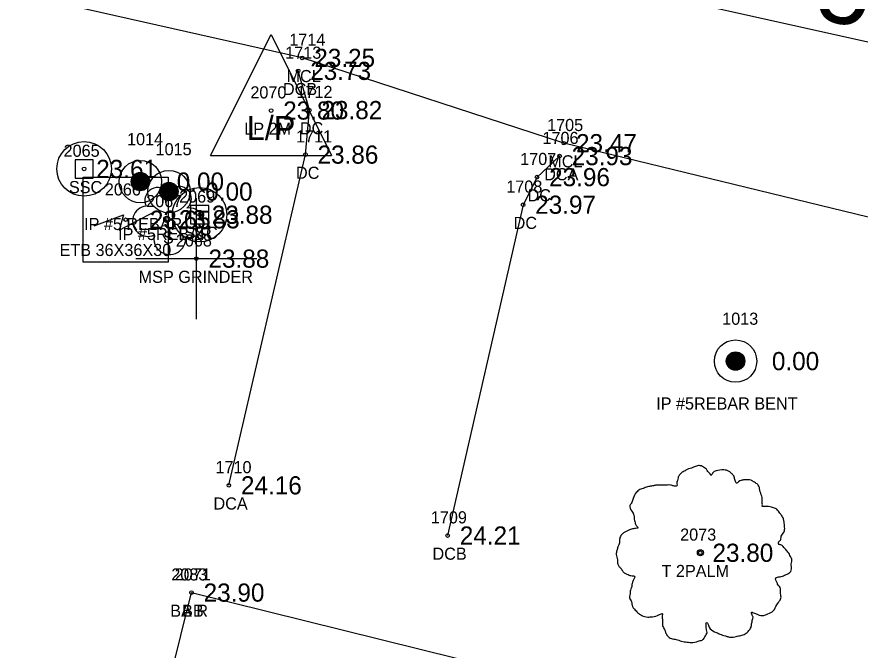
# Model space of a CAD drawing. Extents: x 2654414 to 2656963, y 761776 to 764965.
# Drawn here: x 2655340.6 to 2655410.2, y 762159.7 to 762212 of the extents above; entities that cross this region are included whole.
import ezdxf

# ---------------------------------------------------------------- set-up
doc = ezdxf.new("R2010")
doc.units = 0
for name, color, linetype in [('RD_EX_Bldg', 7, 'Continuous'), ('RD_EX_Bldg_txCode', 7, 'Continuous'), ('RD_EX_Conc', 7, 'Continuous'), ('RD_EX_Conc_txCode', 7, 'Continuous'), ('RD_EX_DV_Prop_txCode', 7, 'Continuous'), ('RD_EX_DV_PropPin', 7, 'Continuous'), ('RD_EX_Misc', 7, 'Continuous'), ('RD_EX_Misc_txCode', 7, 'Continuous'), ('RD_EX_TX_Bldg_ELEV', 7, 'Continuous'), ('RD_EX_TX_Conc_ELEV', 7, 'Continuous'), ('RD_EX_TX_DV_Prop_ELEV', 7, 'Continuous'), ('RD_EX_TX_Misc_ELEV', 7, 'Continuous'), ('RD_EX_TX_UT_ELEV', 7, 'Continuous'), ('RD_EX_TX_VEG_ELEV', 7, 'Continuous'), ('RD_EX_UT', 7, 'Continuous'), ('RD_EX_UT_txCode', 7, 'Continuous'), ('RD_EX_VEG', 7, 'Continuous'), ('RD_EX_VEG_txCode', 7, 'Continuous'), ('RD_HC_Cl', 7, 'Continuous'), ('RD_HC_Data', 7, 'Continuous'), ('RD_SMD_Locator', 7, 'Continuous')]:
    doc.layers.add(name, color=color, linetype=linetype)

msp = doc.modelspace()

# ---------------------------------------------------------------- linework, layer by layer
at = {"layer": 'RD_EX_Bldg'}
msp.add_lwpolyline([(2655355.022, 762164.47), (2655405.088, 762152.061), (2655393.54, 762105.47), (2655343.474, 762117.88), (2655355.022, 762164.47)], dxfattribs=at)
at = {"layer": 'RD_EX_Conc'}
for points in [[(2655440.54, 762187.622), (2655439.059, 762188.617), (2655385.758, 762201.571), (2655364.155, 762208.612), (2655337.932, 762214.524), (2655306.963, 762222.49), (2655288.125, 762231.245)], [(2655358.103, 762173.325), (2655364.425, 762200.628), (2655364.748, 762204.303), (2655363.82, 762207.541)], [(2655385.399, 762200.505), (2655383.539, 762198.768), (2655382.389, 762196.489), (2655376.164, 762169.181)]]:
    msp.add_lwpolyline(points, dxfattribs=at)
at = {"layer": 'RD_EX_DV_PropPin'}
for p, q in [((2655350.102, 762198.103), (2655350.102, 762198.699)), ((2655350.137, 762198.032), (2655350.137, 762198.771)), ((2655350.172, 762197.975), (2655350.172, 762198.828)), ((2655350.207, 762197.927), (2655350.207, 762198.875)), ((2655350.242, 762197.886), (2655350.242, 762198.916)), ((2655350.277, 762197.851), (2655350.277, 762198.952)), ((2655350.312, 762197.819), (2655350.312, 762198.983)), ((2655350.347, 762197.791), (2655350.347, 762199.011)), ((2655350.382, 762197.767), (2655350.382, 762199.036)), ((2655350.417, 762197.745), (2655350.417, 762199.058)), ((2655350.452, 762197.726), (2655350.452, 762199.077)), ((2655350.487, 762197.709), (2655350.487, 762199.094)), ((2655350.522, 762197.694), (2655350.522, 762199.109)), ((2655350.557, 762197.681), (2655350.557, 762199.122)), ((2655350.592, 762197.67), (2655350.592, 762199.133)), ((2655350.627, 762197.661), (2655350.627, 762199.142)), ((2655350.662, 762197.653), (2655350.662, 762199.149)), ((2655350.697, 762197.648), (2655350.697, 762199.155)), ((2655350.732, 762197.644), (2655350.732, 762199.159)), ((2655350.767, 762197.641), (2655350.767, 762199.162)), ((2655350.802, 762197.64), (2655350.802, 762199.162)), ((2655350.837, 762197.641), (2655350.837, 762199.162)), ((2655350.872, 762197.644), (2655350.872, 762199.159)), ((2655350.907, 762197.648), (2655350.907, 762199.155)), ((2655350.942, 762197.653), (2655350.942, 762199.149)), ((2655350.977, 762197.661), (2655350.977, 762199.142)), ((2655351.012, 762197.67), (2655351.012, 762199.133)), ((2655351.047, 762197.681), (2655351.047, 762199.122)), ((2655351.082, 762197.694), (2655351.082, 762199.109)), ((2655351.117, 762197.709), (2655351.117, 762199.094)), ((2655351.152, 762197.726), (2655351.152, 762199.077)), ((2655351.187, 762197.745), (2655351.187, 762199.058)), ((2655351.222, 762197.767), (2655351.222, 762199.036)), ((2655351.257, 762197.791), (2655351.257, 762199.011)), ((2655351.292, 762197.819), (2655351.292, 762198.983)), ((2655351.327, 762197.851), (2655351.327, 762198.952)), ((2655351.362, 762197.886), (2655351.362, 762198.916)), ((2655351.397, 762197.927), (2655351.397, 762198.875)), ((2655351.432, 762197.975), (2655351.432, 762198.828)), ((2655351.467, 762198.032), (2655351.467, 762198.771)), ((2655351.502, 762198.103), (2655351.502, 762198.699)), ((2655350.067, 762198.205), (2655350.067, 762198.597)), ((2655351.537, 762198.205), (2655351.537, 762198.597)), ((2655352.528, 762197.15), (2655352.528, 762198.003)), ((2655352.563, 762197.102), (2655352.563, 762198.051)), ((2655352.598, 762197.061), (2655352.598, 762198.091)), ((2655352.633, 762197.026), (2655352.633, 762198.127)), ((2655352.668, 762196.994), (2655352.668, 762198.159)), ((2655352.703, 762196.967), (2655352.703, 762198.186)), ((2655352.738, 762196.942), (2655352.738, 762198.211)), ((2655352.773, 762196.92), (2655352.773, 762198.233)), ((2655352.808, 762196.901), (2655352.808, 762198.252)), ((2655352.843, 762196.884), (2655352.843, 762198.269)), ((2655352.878, 762196.869), (2655352.878, 762198.284)), ((2655352.913, 762196.856), (2655352.913, 762198.297)), ((2655352.948, 762196.845), (2655352.948, 762198.308)), ((2655352.983, 762196.836), (2655352.983, 762198.317)), ((2655353.018, 762196.828), (2655353.018, 762198.324)), ((2655353.053, 762196.823), (2655353.053, 762198.33)), ((2655353.088, 762196.819), (2655353.088, 762198.334)), ((2655353.123, 762196.816), (2655353.123, 762198.337)), ((2655353.158, 762196.815), (2655353.158, 762198.337)), ((2655353.193, 762196.816), (2655353.193, 762198.337)), ((2655353.228, 762196.819), (2655353.228, 762198.334)), ((2655353.263, 762196.823), (2655353.263, 762198.33)), ((2655353.298, 762196.828), (2655353.298, 762198.324)), ((2655353.333, 762196.836), (2655353.333, 762198.317)), ((2655353.368, 762196.845), (2655353.368, 762198.308)), ((2655353.403, 762196.856), (2655353.403, 762198.297)), ((2655353.438, 762196.869), (2655353.438, 762198.284)), ((2655353.474, 762196.884), (2655353.474, 762198.269)), ((2655353.509, 762196.901), (2655353.509, 762198.252)), ((2655353.544, 762196.92), (2655353.544, 762198.233)), ((2655353.579, 762196.942), (2655353.579, 762198.211)), ((2655353.614, 762196.967), (2655353.614, 762198.186)), ((2655353.649, 762196.994), (2655353.649, 762198.159)), ((2655353.684, 762197.026), (2655353.684, 762198.127)), ((2655353.719, 762197.061), (2655353.719, 762198.091)), ((2655353.754, 762197.102), (2655353.754, 762198.051)), ((2655353.789, 762197.15), (2655353.789, 762198.003)), ((2655352.423, 762197.38), (2655352.423, 762197.773)), ((2655352.458, 762197.278), (2655352.458, 762197.874)), ((2655352.493, 762197.207), (2655352.493, 762197.946)), ((2655353.824, 762197.207), (2655353.824, 762197.946)), ((2655353.859, 762197.278), (2655353.859, 762197.874)), ((2655353.894, 762197.38), (2655353.894, 762197.773)), ((2655399.331, 762183.105), (2655399.331, 762184.054)), ((2655399.366, 762183.064), (2655399.366, 762184.095)), ((2655399.401, 762183.029), (2655399.401, 762184.13)), ((2655399.436, 762182.997), (2655399.436, 762184.162)), ((2655399.471, 762182.97), (2655399.471, 762184.189)), ((2655399.506, 762182.945), (2655399.506, 762184.214)), ((2655399.541, 762182.923), (2655399.541, 762184.236)), ((2655399.576, 762182.904), (2655399.576, 762184.255)), ((2655399.611, 762182.887), (2655399.611, 762184.272)), ((2655399.646, 762182.872), (2655399.646, 762184.287)), ((2655399.681, 762182.859), (2655399.681, 762184.3)), ((2655399.716, 762182.848), (2655399.716, 762184.311)), ((2655399.751, 762182.839), (2655399.751, 762184.32)), ((2655399.786, 762182.831), (2655399.786, 762184.328)), ((2655399.821, 762182.826), (2655399.821, 762184.333)), ((2655399.856, 762182.822), (2655399.856, 762184.337)), ((2655399.891, 762182.819), (2655399.891, 762184.34)), ((2655399.926, 762182.818), (2655399.926, 762184.341)), ((2655399.961, 762182.819), (2655399.961, 762184.34)), ((2655399.996, 762182.822), (2655399.996, 762184.337)), ((2655400.031, 762182.826), (2655400.031, 762184.333)), ((2655400.066, 762182.831), (2655400.066, 762184.328)), ((2655400.101, 762182.839), (2655400.101, 762184.32)), ((2655400.136, 762182.848), (2655400.136, 762184.311)), ((2655400.171, 762182.859), (2655400.171, 762184.3)), ((2655400.206, 762182.872), (2655400.206, 762184.287)), ((2655400.242, 762182.887), (2655400.242, 762184.272)), ((2655400.277, 762182.904), (2655400.277, 762184.255)), ((2655400.312, 762182.923), (2655400.312, 762184.236)), ((2655400.347, 762182.945), (2655400.347, 762184.214)), ((2655400.382, 762182.97), (2655400.382, 762184.189)), ((2655400.417, 762182.997), (2655400.417, 762184.162)), ((2655400.452, 762183.029), (2655400.452, 762184.13)), ((2655400.487, 762183.064), (2655400.487, 762184.095)), ((2655400.522, 762183.105), (2655400.522, 762184.054)), ((2655399.191, 762183.383), (2655399.191, 762183.776)), ((2655399.226, 762183.282), (2655399.226, 762183.877)), ((2655399.261, 762183.21), (2655399.261, 762183.949)), ((2655399.296, 762183.153), (2655399.296, 762184.006)), ((2655400.557, 762183.153), (2655400.557, 762184.006)), ((2655400.592, 762183.21), (2655400.592, 762183.949)), ((2655400.627, 762183.282), (2655400.627, 762183.877)), ((2655400.662, 762183.383), (2655400.662, 762183.776))]:
    msp.add_line(p, q, dxfattribs=at)
for centre, radius in [((2655350.802, 762198.401), 1.75), ((2655350.802, 762198.401), 0.761), ((2655353.158, 762197.576), 1.75), ((2655353.158, 762197.576), 0.761), ((2655399.926, 762183.579), 1.75), ((2655399.926, 762183.579), 0.761)]:
    msp.add_circle(centre, radius, dxfattribs=at)
at = {"layer": 'RD_EX_Misc'}
for p, q in [((2655355.422, 762187.04), (2655355.422, 762197.04)), ((2655350.422, 762192.04), (2655360.422, 762192.04))]:
    msp.add_line(p, q, dxfattribs=at)
at = {"layer": 'RD_EX_UT'}
for p, q in [((2655356.589, 762200.542), (2655361.589, 762210.542)), ((2655361.589, 762210.542), (2655366.589, 762200.542)), ((2655346.905, 762200.196), (2655345.405, 762200.196)), ((2655345.405, 762200.196), (2655345.405, 762198.696)), ((2655346.905, 762198.696), (2655346.905, 762200.196)), ((2655356.589, 762200.542), (2655366.589, 762200.542)), ((2655345.405, 762198.696), (2655346.905, 762198.696)), ((2655356.441, 762196.415), (2655354.941, 762196.415)), ((2655354.941, 762196.415), (2655354.941, 762194.915)), ((2655356.441, 762194.915), (2655356.441, 762196.415)), ((2655354.941, 762194.915), (2655356.441, 762194.915))]:
    msp.add_line(p, q, dxfattribs=at)
msp.add_lwpolyline([(2655346.085, 762191.755), (2655346.085, 762198.755), (2655353.085, 762198.755), (2655353.085, 762191.755)], close=True, dxfattribs=at)
msp.add_lwpolyline([(2655346.983, 762194.749), (2655349.406, 762195.649), (2655349.06, 762194.403), (2655352.105, 762195.996)], dxfattribs=at)
for centre in [(2655346.155, 762199.446), (2655355.691, 762195.665)]:
    msp.add_circle(centre, 2.25, dxfattribs=at)
at = {"layer": 'RD_EX_VEG'}
for centre, radius in [((2655352.975, 762195.29), 0.25), ((2655397.023, 762167.757), 0.25), ((2655397.011, 762167.738), 0.0001)]:
    msp.add_circle(centre, radius, dxfattribs=at)
for centre, radius, start, end in [((2655354.021, 762196.992), 0.995, 308.76261, 152.04674), ((2655352.254, 762196.837), 1.084, 34.97629, 204.75602), ((2655351.412, 762195.134), 1.257, 96.45179, 294.73401), ((2655354.815, 762195.01), 1.218, 256.56668, 98.10463), ((2655353.221, 762193.693), 1.318, 166.88266, 5.75893)]:
    msp.add_arc(centre, radius, start, end, dxfattribs=at)
for points in [[(2655397.155, 762174.924), (2655396.855, 762174.949), (2655396.53, 762174.849), (2655396.28, 762174.749), (2655396.056, 762174.674), (2655395.831, 762174.574), (2655395.531, 762174.399), (2655395.306, 762174.199), (2655395.181, 762173.949), (2655395.131, 762173.724), (2655395.081, 762173.45), (2655395.081, 762173.275), (2655394.956, 762173.25), (2655394.806, 762173.275), (2655394.556, 762173.35), (2655394.306, 762173.35), (2655394.056, 762173.35), (2655393.707, 762173.325), (2655393.357, 762173.325), (2655393.082, 762173.275), (2655392.757, 762173.225), (2655392.382, 762173.1), (2655392.032, 762172.975), (2655391.732, 762172.725), (2655391.483, 762172.25), (2655391.358, 762171.9), (2655391.208, 762171.65), (2655391.358, 762171.201), (2655391.533, 762170.851), (2655391.557, 762170.651), (2655391.632, 762170.226), (2655391.732, 762170.001), (2655391.857, 762169.801), (2655391.782, 762169.776), (2655391.408, 762169.726), (2655391.108, 762169.626), (2655390.683, 762169.401), (2655390.458, 762169.176), (2655390.358, 762168.851), (2655390.333, 762168.502), (2655390.233, 762168.302), (2655390.158, 762168.027), (2655390.133, 762167.952), (2655390.083, 762167.627), (2655390.183, 762167.177), (2655390.208, 762166.827), (2655390.333, 762166.602), (2655390.483, 762166.428), (2655390.658, 762166.178), (2655391.058, 762165.953), (2655391.383, 762165.853), (2655391.582, 762165.828), (2655391.408, 762165.328), (2655391.358, 762164.978), (2655391.233, 762164.578), (2655391.233, 762164.503), (2655391.183, 762164.029), (2655391.333, 762163.704), (2655391.408, 762163.329), (2655391.582, 762163.104), (2655391.857, 762162.804), (2655392.182, 762162.579), (2655392.682, 762162.454), (2655393.082, 762162.479), (2655393.657, 762162.654), (2655393.906, 762162.729), (2655393.881, 762162.554), (2655393.906, 762162.179), (2655393.906, 762161.755), (2655394.056, 762161.43), (2655394.156, 762161.155), (2655394.306, 762160.905), (2655394.631, 762160.68), (2655395.031, 762160.605), (2655395.456, 762160.455), (2655395.906, 762160.38), (2655396.405, 762160.355), (2655397.005, 762160.505), (2655397.28, 762160.63), (2655397.38, 762160.805), (2655397.58, 762161.18), (2655397.53, 762161.405), (2655397.555, 762162.005), (2655397.655, 762161.83), (2655397.83, 762161.48), (2655398.33, 762161.18), (2655398.729, 762161.005), (2655399.204, 762160.855), (2655399.504, 762160.78), (2655399.979, 762160.855), (2655400.354, 762160.93), (2655400.728, 762161.055), (2655401.028, 762161.33), (2655401.203, 762161.605), (2655401.253, 762161.88), (2655401.328, 762162.254), (2655401.378, 762162.429)], [(2655401.378, 762162.429), (2655401.303, 762162.604), (2655401.253, 762162.854), (2655401.328, 762162.829), (2655401.503, 762162.779), (2655401.778, 762162.654), (2655402.003, 762162.579), (2655402.328, 762162.604), (2655402.603, 762162.704), (2655403.052, 762162.979), (2655403.327, 762163.454), (2655403.602, 762163.854), (2655403.677, 762164.179), (2655403.627, 762164.403), (2655403.602, 762164.903), (2655403.402, 762165.153), (2655403.352, 762165.278), (2655403.252, 762165.678), (2655403.327, 762165.728), (2655403.602, 762165.778), (2655403.977, 762165.903), (2655404.252, 762166.028), (2655404.477, 762166.203), (2655404.552, 762166.428), (2655404.527, 762166.827), (2655404.577, 762167.227), (2655404.502, 762167.377), (2655404.402, 762167.527), (2655404.327, 762167.727), (2655404.177, 762167.877), (2655404.077, 762168.027), (2655403.977, 762168.127), (2655403.852, 762168.277), (2655403.677, 762168.402), (2655403.527, 762168.452), (2655403.477, 762168.602), (2655403.627, 762168.802), (2655403.677, 762168.901), (2655403.702, 762169.126), (2655403.927, 762169.476), (2655403.977, 762169.876), (2655403.927, 762170.301), (2655403.877, 762170.576), (2655403.727, 762170.851), (2655403.527, 762171.101), (2655403.402, 762171.275), (2655403.227, 762171.4), (2655402.903, 762171.525), (2655402.653, 762171.575), (2655402.303, 762171.575), (2655402.103, 762171.625), (2655402.128, 762171.675), (2655402.128, 762171.825), (2655402.128, 762172.1), (2655402.053, 762172.55), (2655401.903, 762173.05), (2655401.903, 762173.075), (2655401.803, 762173.325), (2655401.578, 762173.524), (2655401.403, 762173.624), (2655401.203, 762173.749), (2655400.953, 762173.774), (2655400.654, 762173.774), (2655400.379, 762173.724), (2655400.179, 762173.624), (2655400.004, 762173.499), (2655399.929, 762173.649), (2655399.829, 762173.949), (2655399.779, 762174.099), (2655399.629, 762174.274), (2655399.404, 762174.474), (2655398.954, 762174.599), (2655398.33, 762174.524), (2655398.03, 762174.324), (2655397.88, 762174.149), (2655397.83, 762174.274), (2655397.63, 762174.474), (2655397.53, 762174.649), (2655397.355, 762174.774), (2655397.205, 762174.874), (2655397.105, 762174.924)]]:
    msp.add_spline(points, degree=3, dxfattribs=at)
at = {"layer": 'RD_HC_Cl'}
msp.add_line((2655476.255, 762195.138), (2655321.054, 762230.163), dxfattribs=at)
at = {"layer": 'RD_SMD_Locator'}
for centre in [(2655364.155, 762208.612), (2655363.82, 762207.541), (2655361.589, 762204.266), (2655364.748, 762204.303), (2655385.758, 762201.571), (2655364.425, 762200.628), (2655385.399, 762200.505), (2655346.155, 762199.446), (2655383.539, 762198.768), (2655350.802, 762198.401), (2655353.158, 762197.576), (2655382.389, 762196.489), (2655349.585, 762195.255), (2655352.975, 762195.29), (2655355.691, 762195.665), (2655355.422, 762192.04), (2655399.926, 762183.579), (2655358.103, 762173.325), (2655376.164, 762169.181), (2655397.023, 762167.757), (2655355.022, 762164.47), (2655355.022, 762164.47)]:
    msp.add_circle(centre, 0.15, dxfattribs=at)

# ---------------------------------------------------------------- texts
at = {"layer": 'RD_EX_Bldg_txCode'}
for s, p in [('2083', (2655353.353, 762165.47)), ('2071', (2655353.636, 762165.47)), ('BA R', (2655353.266, 762162.47)), ('BB', (2655354.243, 762162.47))]:
    msp.add_text(s, height=1, dxfattribs=at).set_placement(p)
at = {"layer": 'RD_EX_Conc_txCode'}
for s, p in [('1714', (2655363.092, 762209.612)), ('1713', (2655362.757, 762208.541)), ('MCL', (2655362.863, 762206.612)), ('DCB', (2655362.568, 762205.541)), ('1712', (2655363.685, 762205.303)), ('1705', (2655384.372, 762202.571)), ('DC', (2655363.968, 762202.303)), ('1711', (2655363.645, 762201.628)), ('1706', (2655383.99, 762201.505)), ('1707', (2655382.153, 762199.768)), ('MCL', (2655384.467, 762199.571)), ('DC', (2655363.645, 762198.628)), ('DCA', (2655384.131, 762198.505)), ('1708', (2655381.003, 762197.489)), ('DC', (2655382.759, 762196.768)), ('DC', (2655381.609, 762194.489)), ('1710', (2655357, 762174.325)), ('DCA', (2655356.835, 762171.325)), ('1709', (2655374.778, 762170.181)), ('DCB', (2655374.912, 762167.181))]:
    msp.add_text(s, height=1, dxfattribs=at).set_placement(p)
at = {"layer": 'RD_EX_DV_Prop_txCode'}
for s, p in [('1014', (2655349.7, 762201.401)), ('1015', (2655352.056, 762200.576)), ('IP #5 REBAR', (2655346.156, 762194.401)), ('IP #5REBAR', (2655348.962, 762193.576)), ('1013', (2655398.824, 762186.58)), ('IP #5REBAR BENT', (2655393.375, 762179.58))]:
    msp.add_text(s, height=1, dxfattribs=at).set_placement(p)
at = {"layer": 'RD_EX_Misc_txCode'}
for s, p in [('2068', (2655353.729, 762193.04)), ('MSP GRINDER', (2655350.658, 762190.04))]:
    msp.add_text(s, height=1, dxfattribs=at).set_placement(p)
at = {"layer": 'RD_EX_TX_Bldg_ELEV'}
msp.add_text('23.90', height=1.5, dxfattribs=at).set_placement((2655356.022, 762163.72))
msp.add_text('23.90', height=1.5, dxfattribs=at).set_placement((2655356.022, 762163.72))
at = {"layer": 'RD_EX_TX_Conc_ELEV'}
for s, p in [('23.25', (2655365.155, 762207.862)), ('23.73', (2655364.82, 762206.791)), ('23.82', (2655365.748, 762203.553)), ('23.47', (2655386.758, 762200.821)), ('23.86', (2655365.425, 762199.878)), ('23.93', (2655386.399, 762199.755)), ('23.96', (2655384.539, 762198.018)), ('23.97', (2655383.389, 762195.739)), ('24.16', (2655359.103, 762172.575)), ('24.21', (2655377.164, 762168.431))]:
    msp.add_text(s, height=1.5, dxfattribs=at).set_placement(p)
at = {"layer": 'RD_EX_TX_DV_Prop_ELEV'}
for p in [(2655353.802, 762197.651), (2655356.158, 762196.826), (2655402.926, 762182.83)]:
    msp.add_text('0.00', height=1.5, dxfattribs=at).set_placement(p)
at = {"layer": 'RD_EX_TX_Misc_ELEV'}
msp.add_text('23.88', height=1.5, dxfattribs=at).set_placement((2655356.422, 762191.29))
at = {"layer": 'RD_EX_TX_UT_ELEV'}
for s, p in [('23.80', (2655362.589, 762203.516)), ('23.61', (2655347.155, 762198.696)), ('23.65', (2655351.585, 762194.505)), ('23.88', (2655356.691, 762194.915))]:
    msp.add_text(s, height=1.5, dxfattribs=at).set_placement(p)
at = {"layer": 'RD_EX_TX_VEG_ELEV'}
for s, p in [('23.83', (2655353.975, 762194.54)), ('23.80', (2655398.023, 762167.007))]:
    msp.add_text(s, height=1.5, dxfattribs=at).set_placement(p)
at = {"layer": 'RD_EX_UT'}
msp.add_text('L/P', height=2, dxfattribs=at).set_placement((2655359.58, 762201.823))
at = {"layer": 'RD_EX_UT_txCode'}
for s, p in [('2070', (2655359.88, 762205.266)), ('LP 2M', (2655359.377, 762202.266)), ('2065', (2655344.462, 762200.446)), ('SSC', (2655344.903, 762197.446)), ('2066', (2655347.868, 762197.255)), ('2069', (2655353.998, 762196.665)), ('SSC', (2655354.439, 762193.665)), ('ETB 36X36X30', (2655344.128, 762192.255))]:
    msp.add_text(s, height=1, dxfattribs=at).set_placement(p)
at = {"layer": 'RD_EX_VEG_txCode'}
for s, p in [('2067', (2655351.282, 762196.29)), ('S', (2655352.668, 762193.29)), ('2073', (2655395.354, 762168.757)), ('T 2PALM', (2655393.818, 762165.757))]:
    msp.add_text(s, height=1, dxfattribs=at).set_placement(p)
at = {"layer": 'RD_HC_Data'}
msp.add_text('N 77%%d 16\' 59" W', height=6, rotation=347.28301, dxfattribs=at).set_placement((2655372.03, 762219.684))

doc.saveas('drawing.dxf')
